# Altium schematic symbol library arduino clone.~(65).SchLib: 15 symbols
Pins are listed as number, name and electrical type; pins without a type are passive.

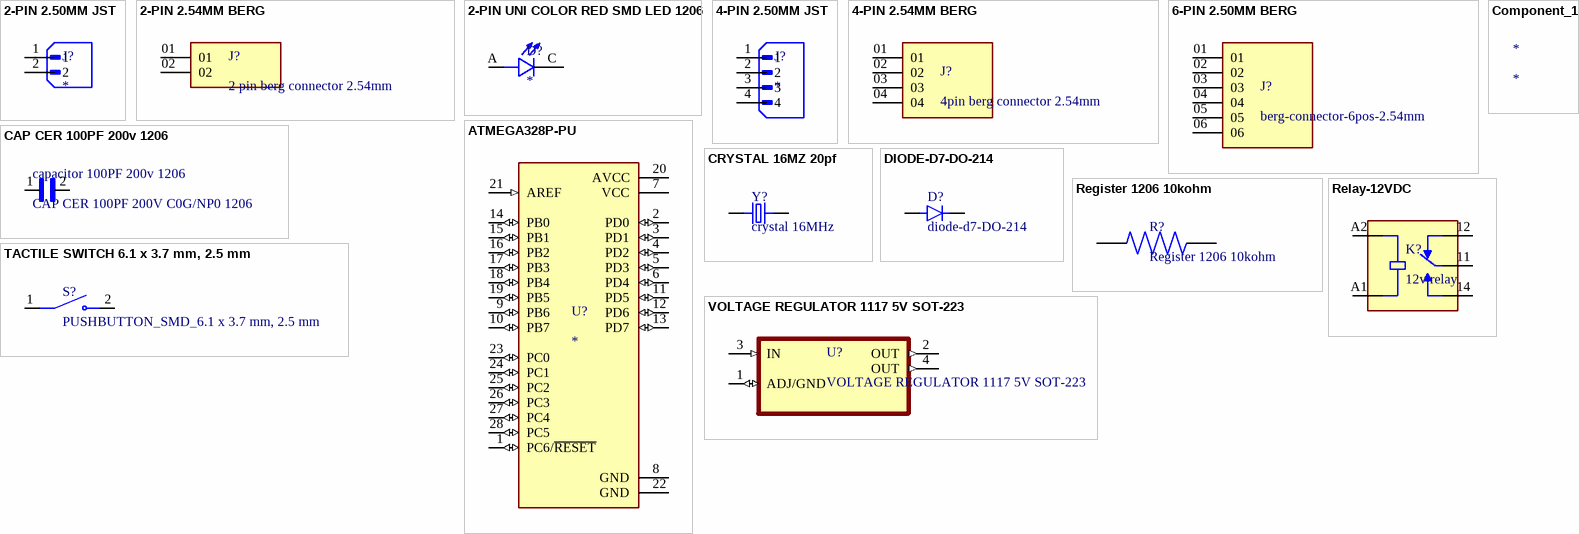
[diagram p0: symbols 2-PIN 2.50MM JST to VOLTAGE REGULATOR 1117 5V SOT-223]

## 2-PIN 2.50MM JST
designator J?
Connector Header Through Hole 2 position 0.098 (2.50mm); MF: JST Sales; MP: B2B-XH-A(LF)(SN)
footprint JST_B2B-XH-A(LF)(SN)
pins: 1, 2

## 2-PIN 2.54MM BERG
designator J?, comment 2 pin berg connector 2.54mm
2 pin berg connector 2.54mm MTLW-102-08-L-S-300
footprint SAMTEC_MTLW-102-08-L-S-300
pins: 01, 02

## 2-PIN UNI COLOR RED SMD LED 1206
designator D?
LED Uni-Color Red 660nm 2-Pin SMD T/R; MP: BR1102W-TR
footprint LED_BR1102W-TR
pins: A, C

## 4-PIN 2.50MM JST
designator J?
Connector Header Through Hole 4 position 0.098 (2.50mm); MF: JST Sales; MP: B4B-XH-A
footprint JST_B4B-XH-A
pins: 1, 2, 3, 4

## 4-PIN 2.54MM BERG
designator J?, comment 4pin berg connector 2.54mm
4 pin berg connector 2.54mm MTSW-104-22-S-S-415
footprint SAMTEC_MTSW-104-22-S-S-415
pins: 01, 02, 03, 04

## 6-PIN 2.50MM BERG
designator J?, comment berg-connector-6pos-2.54mm
MF: Samtec; MP: SSQ-106-02-G-S-LL
footprint berg-connector-6pin-2.54mm
pins: 01, 02, 03, 04, 05, 06

## ATMEGA328P-PU
designator U?
ATmega Series 20 MHz 32 KB Flash 2 KB SRAM 8-Bit Microcontroller - DIP-28; MP: ATMEGA328P-PU
footprint Atmega328pU DIP Controller (Atmega328pU DIP)
pins: 1 PC6/~{RESET} (io), 2 PD0 (io), 3 PD1 (io), 4 PD2 (io), 5 PD3 (io), 6 PD4 (io), 7 VCC (power), 8 GND (power), 9 PB6 (io), 10 PB7 (io), 11 PD5 (io), 12 PD6 (io), 13 PD7 (io), 14 PB0 (io), 15 PB1 (io), 16 PB2 (io), 17 PB3 (io), 18 PB4 (io), 19 PB5 (io), 20 AVCC (power), 21 AREF (in), 22 GND (power), 23 PC0 (io), 24 PC1 (io), 25 PC2 (io), 26 PC3 (io), 27 PC4 (io), 28 PC5 (io)

## CAP CER 100PF 200v 1206
designator capacitor 100PF 200v 1206, comment CAP CER 100PF 200V C0G/NP0 1206
C1206C101J2GACTU CAP CER 100PF 200V C0G/NP0 1206
footprint capacitor 100nF 1206
pins: 1, 2

## Component_1
designator *

## CRYSTAL 16MZ 20pf
designator Y?, comment crystal 16MHz
16 MHz Â±30ppm Crystal 20pF 40 Ohms HC-49/US ECS-160-20-5PX-TR; MF: ECS Inc.
footprint XTAL_ECS-160-20-5PX-TR
pins: 1, 2

## DIODE-D7-DO-214
designator D?, comment diode-d7-DO-214
MF: Diodes Inc.; MP: S1M-13-F
footprint diode-d7-DO-214
pins: A, C

## Register 1206 10kohm
designator R?
MP: RNCF1206BKY10K0
footprint RESC3015X65N (Register)
pins: 1, 2

## Relay-12VDC
designator K?, comment 12v relay
833H Series 10 A SPDT 12 VDC Through Hole Miniature Sugar Cube Power Relay 833H-1C-S-; MF: Song Chuan; MP: 833H-1C-S-12VDC
footprint RELAY_833H-1C-S-12VDC
pins: 11 COM, 12 NC, 14 NO, A1 COIL2, A2 COIL1

## TACTILE SWITCH 6.1 x 3.7 mm, 2.5 mm
designator S?, comment PUSHBUTTON_SMD_6.1 x 3.7 mm, 2.5 mm
6.1 x 3.7 mm, 2.5 mm Actuator Height, 260 gf, Red, Surface Mount, SPST, Tactile Switch TS09-63-25-R-260-SMT-TR; MF: Same Sky
footprint PUSHBUTTON_SMD_6.1 x 3.7 mm, 2.5 mm
pins: 1, 2

## VOLTAGE REGULATOR 1117 5V SOT-223
designator U?
800-mA, 15-V, linear voltage regulator 4-SOT-223 0 to 125 TLV1117-50CDCYRG3; MF: Texas Instruments
footprint SOT230P700X180-4N
pins: 1 ADJ/GND (io), 2 OUT (out), 3 IN (in), 4 OUT (out)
